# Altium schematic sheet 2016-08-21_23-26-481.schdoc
size 406 x 220 mm; SheetNumber: 1; SheetTotal: 1
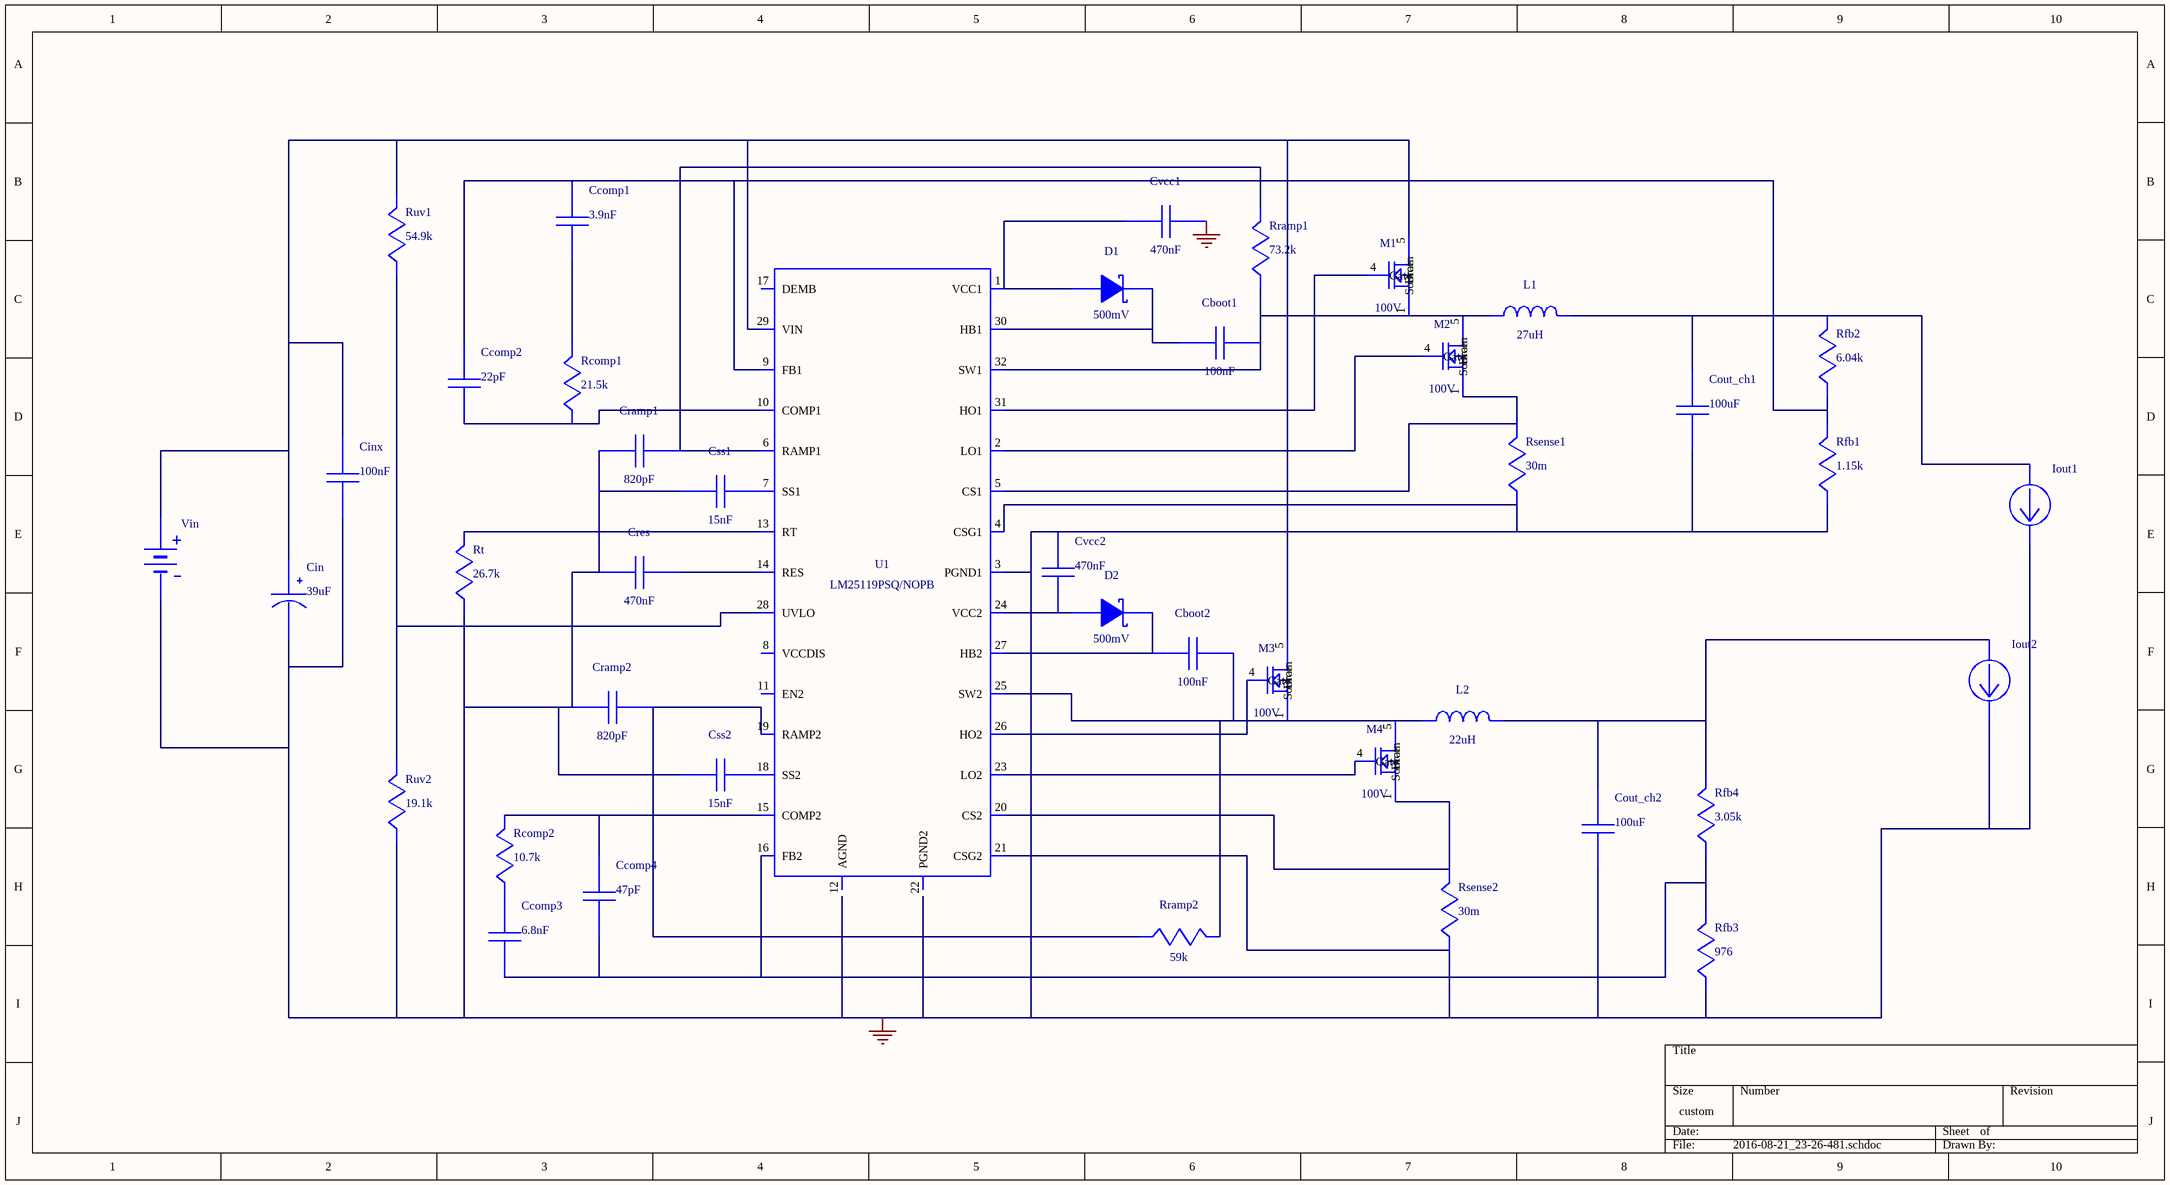
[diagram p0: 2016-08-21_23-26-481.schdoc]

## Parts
Cboot1  value 100nF  (hidden comment: GRM155R61A104KA01D)
Cboot2  value 100nF  (hidden comment: GRM155R61A104KA01D)
Ccomp1  value 3.9nF  (hidden comment: CC0805KRX7R9BB392)
Ccomp2  value 22pF  (hidden comment: C0805C220K3GACTU)
Ccomp3  value 6.8nF  (hidden comment: CC0805KRX7R9BB682)
Ccomp4  value 47pF  (hidden comment: C0805C470K5GACTU)
Cin  value 39uF  (hidden comment: GENERIC_CAP_POLARIZED)
Cinx  value 100nF  (hidden comment: C0805C104K5RACTU)
Cout_ch1  value 100uF  (hidden comment: GRM31CR60J107ME39L)
Cout_ch2  value 100uF  (hidden comment: GRM31CR60J107ME39L)
Cramp1  value 820pF  (hidden comment: CC0805KRX7R9BB821)
Cramp2  value 820pF  (hidden comment: CC0805KRX7R9BB821)
Cres  value 470nF  (hidden comment: GRM155C80J474KE19D)
Css1  value 15nF  (hidden comment: CC0805KRX7R9BB153)
Css2  value 15nF  (hidden comment: CC0805KRX7R9BB153)
Cvcc1  value 470nF  (hidden comment: GRM155R61A474KE15D)
Cvcc2  value 470nF  (hidden comment: GRM155R61A474KE15D)
D1  value 500mV  (hidden comment: SS14-E3/61T)
D2  value 500mV  (hidden comment: SS14-E3/61T)
Iout1  WB_CURRENT_LOAD  (value not drawn)
Iout2  WB_CURRENT_LOAD  (value not drawn)
L1  value 27uH  (hidden comment: SDR1307-270ML)
L2  value 22uH  (hidden comment: SDR1105-220ML)
M1  value 100V  (hidden comment: CSD19537Q3)
M2  value 100V  (hidden comment: CSD19537Q3)
M3  value 100V  (hidden comment: CSD19537Q3)
M4  value 100V  (hidden comment: CSD19537Q3)
Rcomp1  value 21.5k  (hidden comment: CRCW040221K5FKED)
Rcomp2  value 10.7k  (hidden comment: CRCW040210K7FKED)
Rfb1  value 1.15k  (hidden comment: CRCW04021K15FKED)
Rfb2  value 6.04k  (hidden comment: CRCW04026K04FKED)
Rfb3  value 976  (hidden comment: CRCW0402976RFKED)
Rfb4  value 3.05k  (hidden comment: RT0805BRD073K05L)
Rramp1  value 73.2k  (hidden comment: CRCW040273K2FKED)
Rramp2  value 59k  (hidden comment: CRCW040259K0FKED)
Rsense1  value 30m  (hidden comment: CSR1206FK30L0)
Rsense2  value 30m  (hidden comment: CSR1206FK30L0)
Rt  value 26.7k  (hidden comment: CRCW040226K7FKED)
Ruv1  value 54.9k  (hidden comment: CRCW040254K9FKED)
Ruv2  value 19.1k  (hidden comment: CRCW040219K1FKED)
U1  LM25119PSQ/NOPB
Vin  WB_BATTERY  (value not drawn)

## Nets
0: Cin.2(-) Cinx.2 Cout_ch1.2 Cout_ch2.2 Cramp1.2 Cramp2.2 Cres.2 Css1.2 Css2.2 Cvcc1.2 Cvcc2.2 Iout1.2(-) Iout2.2(-) Rfb1.2 Rfb3.2 Rsense1.2 Rsense2.2 Rt.2 Ruv2.2 U1.3(PGND1) U1.4(CSG1) U1.21(CSG2) U1.33(EP) Vin.2(-)
NetCboot1_1: Cboot1.1 L1.1 M1.1(Source) M1.2(Source) M1.3(Source) M2.5(Drain) M2.6(Drain) M2.7(Drain) M2.8(Drain) M2.9(Drain) Rramp1.2 U1.32(SW1)
NetCboot1_2: Cboot1.2 D1.1(K) U1.30(HB1)
NetCboot2_1: Cboot2.1 L2.1 M3.1(Source) M3.2(Source) M3.3(Source) M4.5(Drain) M4.6(Drain) M4.7(Drain) M4.8(Drain) M4.9(Drain) Rramp2.1 U1.25(SW2)
NetCboot2_2: Cboot2.2 D2.1(K) U1.27(HB2)
NetCcomp1_1: Ccomp1.1 Rcomp1.1
NetCcomp1_2: Ccomp1.2 Ccomp2.2 Rfb1.1 Rfb2.2 U1.9(FB1)
NetCcomp2_1: Ccomp2.1 Rcomp1.2 U1.10(COMP1)
NetCcomp3_1: Ccomp3.1 Rcomp2.2
NetCcomp3_2: Ccomp3.2 Ccomp4.2 Rfb3.1 Rfb4.2 U1.16(FB2)
NetCcomp4_1: Ccomp4.1 Rcomp2.1 U1.15(COMP2)
NetCin_1: Cin.1(+) Cinx.1 M1.5(Drain) M1.6(Drain) M1.7(Drain) M1.8(Drain) M1.9(Drain) M3.5(Drain) M3.6(Drain) M3.7(Drain) M3.8(Drain) M3.9(Drain) Ruv1.1 U1.29(VIN) Vin.1(+)
NetCout_ch1_1: Cout_ch1.1 Iout1.1(+) L1.2 Rfb2.1
NetCout_ch2_1: Cout_ch2.1 Iout2.1(+) L2.2 Rfb4.1
NetCramp1_1: Cramp1.1 Rramp1.1 U1.6(RAMP1)
NetCramp2_1: Cramp2.1 Rramp2.2 U1.19(RAMP2)
NetCres_1: Cres.1 U1.14(RES)
NetCss1_1: Css1.1 U1.7(SS1)
NetCss2_1: Css2.1 U1.18(SS2)
NetCvcc1_1: Cvcc1.1 D1.2(A) U1.1(VCC1)
NetCvcc2_1: Cvcc2.1 D2.2(A) U1.24(VCC2)
NetM1_4: M1.4(Gate) U1.31(HO1)
NetM2_1: M2.1(Source) M2.2(Source) M2.3(Source) Rsense1.1 U1.5(CS1)
NetM2_4: M2.4(Gate) U1.2(LO1)
NetM3_4: M3.4(Gate) U1.26(HO2)
NetM4_1: M4.1(Source) M4.2(Source) M4.3(Source) Rsense2.1 U1.20(CS2)
NetM4_4: M4.4(Gate) U1.23(LO2)
NetRt_1: Rt.1 U1.13(RT)
NetRuv1_2: Ruv1.2 Ruv2.1 U1.28(UVLO)

Not connected (* = marked no-connect by the designer): U1 8(VCCDIS) 11(EN2) 12(AGND) 17(DEMB) 22(PGND2)

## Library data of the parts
Cboot1 Cboot2 = GRM155R61A104KA01D: GRM155R61A104KA0; Manufacturer Name: MuRata
Ccomp1 = CC0805KRX7R9BB392: CC0805KRX7R9BB39; Manufacturer Name: Yageo America
Ccomp2 = C0805C220K3GACTU: Manufacturer Name: Kemet
Ccomp3 = CC0805KRX7R9BB682: CC0805KRX7R9BB68; Manufacturer Name: Yageo America
Ccomp4 = C0805C470K5GACTU: Manufacturer Name: Kemet
Cin = GENERIC_CAP_POLARIZED: 50SVPF39M; Manufacturer Name: Panasonic
Cinx = C0805C104K5RACTU: Manufacturer Name: Kemet
Cout_ch1 Cout_ch2 = GRM31CR60J107ME39L: GRM31CR60J107ME3; Manufacturer Name: MuRata
Cramp1 Cramp2 = CC0805KRX7R9BB821: CC0805KRX7R9BB82; Manufacturer Name: Yageo America
Cres = GRM155C80J474KE19D: GRM155C80J474KE1; Manufacturer Name: MuRata
Css1 Css2 = CC0805KRX7R9BB153: CC0805KRX7R9BB15; Manufacturer Name: Yageo America
Cvcc1 Cvcc2 = GRM155R61A474KE15D: GRM155R61A474KE1; Manufacturer Name: MuRata
D1 D2 = SS14-E3/61T: Manufacturer Name: Vishay-Semiconductor
L1 = SDR1307-270ML: Manufacturer Name: Bourns
L2 = SDR1105-220ML: Manufacturer Name: Bourns
M1-M4 = CSD19537Q3: Manufacturer Name: Texas Instruments
Rcomp1 = CRCW040221K5FKED: Manufacturer Name: Vishay-Dale
Rcomp2 = CRCW040210K7FKED: Manufacturer Name: Vishay-Dale
Rfb1 = CRCW04021K15FKED: Manufacturer Name: Vishay-Dale
Rfb2 = CRCW04026K04FKED: Manufacturer Name: Vishay-Dale
Rfb3 = CRCW0402976RFKED: Manufacturer Name: Vishay-Dale
Rfb4 = RT0805BRD073K05L: Manufacturer Name: Yageo America
Rramp1 = CRCW040273K2FKED: Manufacturer Name: Vishay-Dale
Rramp2 = CRCW040259K0FKED: Manufacturer Name: Vishay-Dale
Rsense1 Rsense2 = CSR1206FK30L0: Manufacturer Name: Stackpole Electronics Inc
Rt = CRCW040226K7FKED: Manufacturer Name: Vishay-Dale
Ruv1 = CRCW040254K9FKED: Manufacturer Name: Vishay-Dale
Ruv2 = CRCW040219K1FKED: Manufacturer Name: Vishay-Dale
U1 = LM25119PSQ/NOPB: Manufacturer Name: Texas Instruments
